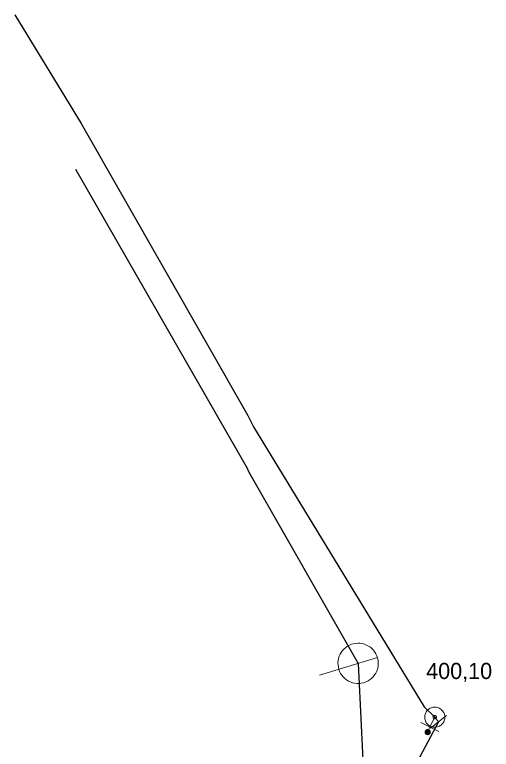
# Model space of a CAD drawing. Extents: x -809028 to -807737, y -990545 to -989489.
# Drawn here: x -808255.02 to -808231.39, y -989691.44 to -989655.02 of the extents above; entities that cross this region are included whole.
import ezdxf

# ---------------------------------------------------------------- set-up
doc = ezdxf.new("R2010")
doc.units = 0
doc.header["$LTSCALE"] = 0.32
for name, color, linetype, lineweight in [('14', 7, 'Continuous', 25), ('17', 7, 'Continuous', 25), ('22', 7, 'Continuous', 13), ('34', 7, 'Continuous', 13), ('47', 7, 'Continuous', 13), ('9', 7, 'Continuous', 13)]:
    doc.layers.add(name, color=color, linetype=linetype, lineweight=lineweight)

msp = doc.modelspace()

# ---------------------------------------------------------------- linework, layer by layer
at = {"layer": '14'}
msp.add_line((-808237.989, -989687.18), (-808237.065, -989706.541), dxfattribs=at)
at = {"layer": '14', "lineweight": 13}
for p, q in [((-808234.19, -989689.849), (-808234.43, -989690.329)), ((-808234.19, -989689.849), (-808234.009, -989690.079)), ((-808234.43, -989690.329), (-808234.539, -989690.589))]:
    msp.add_line(p, q, dxfattribs=at)
at = {"layer": '14'}
msp.add_lwpolyline([(-808252.009, -989662.67), (-808243.5, -989677.51), (-808243.42, -989677.67), (-808237.989, -989687.18)], dxfattribs=at)
at = {"layer": '17'}
msp.add_line((-808234.009, -989690.079), (-808240.249, -989701.76), dxfattribs=at)
msp.add_lwpolyline([(-808255.02, -989655.019), (-808251.73, -989660.41), (-808243.46, -989674.89), (-808243.18, -989675.46), (-808234.71, -989689.329), (-808234.19, -989689.849)], dxfattribs=at)
at = {"layer": '22'}
msp.add_line((-808239.899, -989687.773), (-808237.034, -989686.883), dxfattribs=at)
msp.add_lwpolyline([(-808237.693, -989688.135), (-808237.59, -989688.097), (-808237.492, -989688.047), (-808237.4, -989687.987), (-808237.315, -989687.919), (-808237.238, -989687.841), (-808237.171, -989687.755), (-808237.113, -989687.662), (-808237.066, -989687.563), (-808237.029, -989687.46), (-808237.004, -989687.354), (-808236.991, -989687.245), (-808236.99, -989687.135), (-808237.001, -989687.026), (-808237.024, -989686.919), (-808237.058, -989686.814), (-808237.104, -989686.715), (-808237.159, -989686.621), (-808237.225, -989686.533), (-808237.301, -989686.454), (-808237.384, -989686.383), (-808237.475, -989686.322), (-808237.572, -989686.271), (-808237.674, -989686.231), (-808237.78, -989686.202), (-808237.887, -989686.185), (-808237.997, -989686.18), (-808238.107, -989686.187), (-808238.214, -989686.206), (-808238.32, -989686.236), (-808238.421, -989686.278), (-808238.517, -989686.33), (-808238.606, -989686.393), (-808238.688, -989686.465), (-808238.763, -989686.546), (-808238.827, -989686.635), (-808238.882, -989686.729), (-808238.926, -989686.83), (-808238.958, -989686.934), (-808238.98, -989687.041), (-808238.989, -989687.151), (-808238.986, -989687.26), (-808238.971, -989687.368), (-808238.944, -989687.475), (-808238.906, -989687.577), (-808238.857, -989687.675), (-808238.798, -989687.767), (-808238.729, -989687.852), (-808238.65, -989687.929), (-808238.565, -989687.997), (-808238.472, -989688.055), (-808238.373, -989688.103), (-808238.27, -989688.139), (-808238.164, -989688.165), (-808238.055, -989688.177), (-808237.946, -989688.179), (-808237.836, -989688.168), (-808237.729, -989688.145)], close=True, dxfattribs=at)
at = {"layer": '34'}
for p, q in [((-808233.615, -989689.77), (-808234.403, -989690.386)), ((-808234.877, -989690.105), (-808233.983, -989690.553))]:
    msp.add_line(p, q, dxfattribs=at)
at = {"layer": '47'}
for points in [[(-808233.836, -989690.202), (-808233.801, -989690.163), (-808233.77, -989690.121), (-808233.745, -989690.075), (-808233.723, -989690.028), (-808233.707, -989689.978), (-808233.696, -989689.926), (-808233.691, -989689.875), (-808233.691, -989689.822), (-808233.696, -989689.771), (-808233.707, -989689.719), (-808233.723, -989689.669), (-808233.745, -989689.622), (-808233.77, -989689.576), (-808233.801, -989689.534), (-808233.836, -989689.495), (-808233.875, -989689.46), (-808233.917, -989689.429), (-808233.963, -989689.403), (-808234.01, -989689.382), (-808234.06, -989689.366), (-808234.112, -989689.355), (-808234.164, -989689.349), (-808234.216, -989689.349), (-808234.268, -989689.354), (-808234.319, -989689.366), (-808234.369, -989689.382), (-808234.417, -989689.403), (-808234.462, -989689.429), (-808234.504, -989689.46), (-808234.543, -989689.495), (-808234.578, -989689.534), (-808234.609, -989689.576), (-808234.636, -989689.622), (-808234.656, -989689.669), (-808234.672, -989689.719), (-808234.684, -989689.77), (-808234.689, -989689.822), (-808234.689, -989689.875), (-808234.684, -989689.927), (-808234.672, -989689.978), (-808234.656, -989690.028), (-808234.636, -989690.075), (-808234.609, -989690.121), (-808234.578, -989690.163), (-808234.543, -989690.202), (-808234.504, -989690.237), (-808234.462, -989690.268), (-808234.417, -989690.294), (-808234.369, -989690.315), (-808234.319, -989690.331), (-808234.268, -989690.343), (-808234.216, -989690.348), (-808234.164, -989690.348), (-808234.112, -989690.342), (-808234.06, -989690.331), (-808234.01, -989690.315), (-808233.963, -989690.294), (-808233.917, -989690.268), (-808233.875, -989690.237)], [(-808234.132, -989689.906), (-808234.125, -989689.9), (-808234.121, -989689.893), (-808234.117, -989689.886), (-808234.113, -989689.878), (-808234.11, -989689.87), (-808234.109, -989689.861), (-808234.107, -989689.853), (-808234.107, -989689.844), (-808234.109, -989689.836), (-808234.11, -989689.827), (-808234.113, -989689.819), (-808234.117, -989689.811), (-808234.121, -989689.804), (-808234.125, -989689.797), (-808234.132, -989689.791), (-808234.138, -989689.784), (-808234.145, -989689.78), (-808234.152, -989689.776), (-808234.16, -989689.772), (-808234.168, -989689.769), (-808234.177, -989689.768), (-808234.185, -989689.766), (-808234.194, -989689.766), (-808234.203, -989689.767), (-808234.211, -989689.769), (-808234.219, -989689.772), (-808234.227, -989689.776), (-808234.234, -989689.78), (-808234.241, -989689.784), (-808234.247, -989689.791), (-808234.254, -989689.797), (-808234.258, -989689.804), (-808234.262, -989689.811), (-808234.266, -989689.819), (-808234.269, -989689.827), (-808234.271, -989689.835), (-808234.272, -989689.844), (-808234.272, -989689.853), (-808234.271, -989689.862), (-808234.269, -989689.87), (-808234.266, -989689.878), (-808234.262, -989689.886), (-808234.258, -989689.893), (-808234.254, -989689.9), (-808234.247, -989689.906), (-808234.241, -989689.913), (-808234.234, -989689.917), (-808234.227, -989689.921), (-808234.219, -989689.925), (-808234.211, -989689.928), (-808234.203, -989689.93), (-808234.194, -989689.931), (-808234.185, -989689.931), (-808234.177, -989689.929), (-808234.168, -989689.928), (-808234.16, -989689.925), (-808234.152, -989689.921), (-808234.145, -989689.917), (-808234.138, -989689.913)]]:
    msp.add_lwpolyline(points, close=True, dxfattribs=at)
at = {"layer": '9'}
for points in [[(-808234.665, -989690.589), (-808234.665, -989690.602), (-808234.663, -989690.615), (-808234.66, -989690.628), (-808234.655, -989690.64), (-808234.649, -989690.652), (-808234.642, -989690.663), (-808234.634, -989690.673), (-808234.624, -989690.683), (-808234.614, -989690.691), (-808234.603, -989690.698), (-808234.591, -989690.704), (-808234.579, -989690.709), (-808234.566, -989690.712), (-808234.553, -989690.714), (-808234.54, -989690.716), (-808234.527, -989690.715), (-808234.514, -989690.713), (-808234.501, -989690.71), (-808234.489, -989690.705), (-808234.477, -989690.699), (-808234.466, -989690.692), (-808234.456, -989690.684), (-808234.446, -989690.674), (-808234.438, -989690.664), (-808234.431, -989690.653), (-808234.425, -989690.641), (-808234.42, -989690.629), (-808234.417, -989690.616), (-808234.415, -989690.603), (-808234.413, -989690.59), (-808234.414, -989690.577), (-808234.416, -989690.564), (-808234.419, -989690.551), (-808234.424, -989690.539), (-808234.429, -989690.527), (-808234.437, -989690.516), (-808234.445, -989690.506), (-808234.455, -989690.496), (-808234.465, -989690.488), (-808234.476, -989690.481), (-808234.488, -989690.475), (-808234.5, -989690.47), (-808234.513, -989690.467), (-808234.526, -989690.465), (-808234.539, -989690.464), (-808234.552, -989690.464), (-808234.565, -989690.466), (-808234.578, -989690.469), (-808234.59, -989690.474), (-808234.602, -989690.48), (-808234.613, -989690.487), (-808234.623, -989690.495), (-808234.633, -989690.505), (-808234.641, -989690.515), (-808234.648, -989690.526), (-808234.654, -989690.538), (-808234.659, -989690.55), (-808234.662, -989690.563), (-808234.664, -989690.576)], [(-808234.645, -989690.589), (-808234.646, -989690.6), (-808234.644, -989690.611), (-808234.641, -989690.622), (-808234.637, -989690.632), (-808234.632, -989690.642), (-808234.626, -989690.651), (-808234.619, -989690.66), (-808234.611, -989690.668), (-808234.602, -989690.675), (-808234.593, -989690.681), (-808234.583, -989690.686), (-808234.573, -989690.69), (-808234.562, -989690.693), (-808234.551, -989690.696), (-808234.54, -989690.696), (-808234.529, -989690.696), (-808234.518, -989690.694), (-808234.507, -989690.691), (-808234.497, -989690.687), (-808234.487, -989690.682), (-808234.478, -989690.676), (-808234.469, -989690.669), (-808234.461, -989690.661), (-808234.454, -989690.652), (-808234.448, -989690.643), (-808234.443, -989690.633), (-808234.439, -989690.623), (-808234.436, -989690.612), (-808234.434, -989690.601), (-808234.433, -989690.59), (-808234.433, -989690.579), (-808234.434, -989690.568), (-808234.438, -989690.557), (-808234.442, -989690.547), (-808234.447, -989690.537), (-808234.453, -989690.528), (-808234.46, -989690.519), (-808234.468, -989690.511), (-808234.477, -989690.504), (-808234.486, -989690.498), (-808234.496, -989690.493), (-808234.505, -989690.489), (-808234.517, -989690.486), (-808234.527, -989690.484), (-808234.539, -989690.484), (-808234.55, -989690.483), (-808234.561, -989690.485), (-808234.572, -989690.488), (-808234.581, -989690.492), (-808234.592, -989690.497), (-808234.601, -989690.503), (-808234.61, -989690.51), (-808234.618, -989690.518), (-808234.625, -989690.527), (-808234.63, -989690.536), (-808234.636, -989690.546), (-808234.64, -989690.556), (-808234.643, -989690.567), (-808234.645, -989690.578)], [(-808234.626, -989690.589), (-808234.626, -989690.598), (-808234.625, -989690.607), (-808234.622, -989690.616), (-808234.619, -989690.624), (-808234.615, -989690.632), (-808234.61, -989690.64), (-808234.603, -989690.647), (-808234.598, -989690.653), (-808234.591, -989690.659), (-808234.583, -989690.664), (-808234.575, -989690.668), (-808234.567, -989690.671), (-808234.558, -989690.674), (-808234.549, -989690.675), (-808234.54, -989690.677), (-808234.531, -989690.676), (-808234.522, -989690.675), (-808234.513, -989690.672), (-808234.505, -989690.669), (-808234.497, -989690.665), (-808234.489, -989690.66), (-808234.482, -989690.654), (-808234.476, -989690.648), (-808234.47, -989690.641), (-808234.465, -989690.633), (-808234.461, -989690.625), (-808234.458, -989690.617), (-808234.455, -989690.608), (-808234.454, -989690.599), (-808234.451, -989690.59), (-808234.453, -989690.581), (-808234.454, -989690.572), (-808234.456, -989690.563), (-808234.46, -989690.555), (-808234.464, -989690.547), (-808234.469, -989690.539), (-808234.475, -989690.532), (-808234.481, -989690.526), (-808234.488, -989690.52), (-808234.496, -989690.515), (-808234.504, -989690.511), (-808234.512, -989690.508), (-808234.521, -989690.505), (-808234.53, -989690.504), (-808234.539, -989690.503), (-808234.548, -989690.503), (-808234.557, -989690.504), (-808234.566, -989690.507), (-808234.574, -989690.51), (-808234.581, -989690.514), (-808234.59, -989690.519), (-808234.597, -989690.525), (-808234.603, -989690.531), (-808234.608, -989690.538), (-808234.614, -989690.546), (-808234.618, -989690.554), (-808234.621, -989690.562), (-808234.624, -989690.571), (-808234.625, -989690.58)], [(-808234.606, -989690.589), (-808234.606, -989690.596), (-808234.605, -989690.603), (-808234.603, -989690.61), (-808234.601, -989690.616), (-808234.598, -989690.622), (-808234.594, -989690.628), (-808234.59, -989690.634), (-808234.585, -989690.639), (-808234.579, -989690.643), (-808234.573, -989690.647), (-808234.567, -989690.65), (-808234.561, -989690.653), (-808234.554, -989690.654), (-808234.547, -989690.657), (-808234.54, -989690.657), (-808234.532, -989690.657), (-808234.526, -989690.655), (-808234.519, -989690.654), (-808234.513, -989690.651), (-808234.505, -989690.648), (-808234.501, -989690.644), (-808234.495, -989690.64), (-808234.49, -989690.635), (-808234.486, -989690.629), (-808234.482, -989690.623), (-808234.478, -989690.617), (-808234.476, -989690.611), (-808234.474, -989690.604), (-808234.473, -989690.597), (-808234.472, -989690.59), (-808234.472, -989690.583), (-808234.473, -989690.576), (-808234.475, -989690.569), (-808234.478, -989690.563), (-808234.481, -989690.556), (-808234.485, -989690.551), (-808234.489, -989690.545), (-808234.494, -989690.54), (-808234.5, -989690.536), (-808234.505, -989690.532), (-808234.512, -989690.529), (-808234.518, -989690.526), (-808234.525, -989690.524), (-808234.532, -989690.523), (-808234.539, -989690.523), (-808234.546, -989690.523), (-808234.553, -989690.523), (-808234.559, -989690.525), (-808234.566, -989690.528), (-808234.572, -989690.531), (-808234.578, -989690.535), (-808234.584, -989690.539), (-808234.589, -989690.544), (-808234.593, -989690.55), (-808234.597, -989690.555), (-808234.6, -989690.562), (-808234.603, -989690.568), (-808234.603, -989690.575), (-808234.606, -989690.582)], [(-808234.586, -989690.589), (-808234.586, -989690.594), (-808234.586, -989690.599), (-808234.585, -989690.604), (-808234.583, -989690.608), (-808234.581, -989690.613), (-808234.578, -989690.617), (-808234.575, -989690.62), (-808234.571, -989690.624), (-808234.568, -989690.627), (-808234.564, -989690.63), (-808234.559, -989690.632), (-808234.554, -989690.634), (-808234.55, -989690.635), (-808234.545, -989690.637), (-808234.54, -989690.637), (-808234.535, -989690.637), (-808234.53, -989690.636), (-808234.525, -989690.635), (-808234.521, -989690.633), (-808234.516, -989690.631), (-808234.512, -989690.628), (-808234.508, -989690.625), (-808234.505, -989690.621), (-808234.502, -989690.618), (-808234.499, -989690.614), (-808234.497, -989690.609), (-808234.495, -989690.605), (-808234.494, -989690.6), (-808234.493, -989690.595), (-808234.492, -989690.59), (-808234.492, -989690.585), (-808234.493, -989690.58), (-808234.494, -989690.575), (-808234.496, -989690.571), (-808234.498, -989690.566), (-808234.501, -989690.562), (-808234.504, -989690.558), (-808234.507, -989690.555), (-808234.511, -989690.552), (-808234.515, -989690.549), (-808234.52, -989690.547), (-808234.524, -989690.545), (-808234.529, -989690.544), (-808234.534, -989690.543), (-808234.539, -989690.543), (-808234.544, -989690.543), (-808234.549, -989690.544), (-808234.554, -989690.544), (-808234.558, -989690.546), (-808234.563, -989690.548), (-808234.567, -989690.551), (-808234.57, -989690.554), (-808234.574, -989690.557), (-808234.576, -989690.561), (-808234.58, -989690.565), (-808234.581, -989690.57), (-808234.584, -989690.574), (-808234.585, -989690.579), (-808234.586, -989690.584)], [(-808234.566, -989690.589), (-808234.566, -989690.592), (-808234.567, -989690.595), (-808234.566, -989690.597), (-808234.565, -989690.6), (-808234.564, -989690.603), (-808234.562, -989690.605), (-808234.559, -989690.607), (-808234.558, -989690.609), (-808234.556, -989690.611), (-808234.554, -989690.613), (-808234.551, -989690.615), (-808234.548, -989690.616), (-808234.546, -989690.616), (-808234.543, -989690.617), (-808234.54, -989690.617), (-808234.537, -989690.617), (-808234.534, -989690.617), (-808234.531, -989690.616), (-808234.529, -989690.615), (-808234.526, -989690.614), (-808234.524, -989690.612), (-808234.521, -989690.61), (-808234.519, -989690.608), (-808234.518, -989690.606), (-808234.516, -989690.604), (-808234.515, -989690.601), (-808234.513, -989690.598), (-808234.513, -989690.596), (-808234.512, -989690.593), (-808234.511, -989690.59), (-808234.512, -989690.587), (-808234.512, -989690.584), (-808234.513, -989690.581), (-808234.514, -989690.579), (-808234.515, -989690.576), (-808234.517, -989690.574), (-808234.518, -989690.571), (-808234.52, -989690.569), (-808234.523, -989690.568), (-808234.525, -989690.566), (-808234.527, -989690.565), (-808234.53, -989690.564), (-808234.532, -989690.563), (-808234.536, -989690.563), (-808234.539, -989690.562), (-808234.542, -989690.563), (-808234.545, -989690.562), (-808234.547, -989690.564), (-808234.55, -989690.564), (-808234.553, -989690.565), (-808234.554, -989690.567), (-808234.557, -989690.568), (-808234.559, -989690.57), (-808234.561, -989690.573), (-808234.563, -989690.575), (-808234.564, -989690.578), (-808234.565, -989690.58), (-808234.566, -989690.583), (-808234.566, -989690.586)], [(-808234.547, -989690.589), (-808234.547, -989690.591), (-808234.547, -989690.591), (-808234.546, -989690.591), (-808234.546, -989690.593), (-808234.547, -989690.594), (-808234.545, -989690.594), (-808234.545, -989690.594), (-808234.545, -989690.596), (-808234.545, -989690.596), (-808234.544, -989690.597), (-808234.542, -989690.597), (-808234.542, -989690.597), (-808234.542, -989690.598), (-808234.54, -989690.598), (-808234.54, -989690.598), (-808234.539, -989690.598), (-808234.538, -989690.598), (-808234.538, -989690.597), (-808234.537, -989690.597), (-808234.535, -989690.597), (-808234.535, -989690.596), (-808234.535, -989690.596), (-808234.534, -989690.595), (-808234.534, -989690.595), (-808234.532, -989690.594), (-808234.532, -989690.593), (-808234.531, -989690.592), (-808234.531, -989690.592), (-808234.531, -989690.591), (-808234.531, -989690.59), (-808234.531, -989690.589), (-808234.531, -989690.588), (-808234.531, -989690.588), (-808234.532, -989690.587), (-808234.532, -989690.586), (-808234.532, -989690.585), (-808234.532, -989690.585), (-808234.534, -989690.584), (-808234.534, -989690.584), (-808234.535, -989690.583), (-808234.536, -989690.583), (-808234.537, -989690.582), (-808234.537, -989690.582), (-808234.538, -989690.582), (-808234.539, -989690.582), (-808234.54, -989690.582), (-808234.541, -989690.582), (-808234.541, -989690.582), (-808234.542, -989690.583), (-808234.543, -989690.582), (-808234.544, -989690.584), (-808234.544, -989690.584), (-808234.545, -989690.584), (-808234.545, -989690.584), (-808234.546, -989690.586), (-808234.546, -989690.587), (-808234.546, -989690.588), (-808234.547, -989690.588), (-808234.547, -989690.589)]]:
    msp.add_lwpolyline(points, close=True, dxfattribs=at)

# ---------------------------------------------------------------- texts
at = {"layer": '14'}
msp.add_text('400,10', height=0.8, dxfattribs=at).set_placement((-808234.616, -989687.956))

doc.saveas('drawing.dxf')
